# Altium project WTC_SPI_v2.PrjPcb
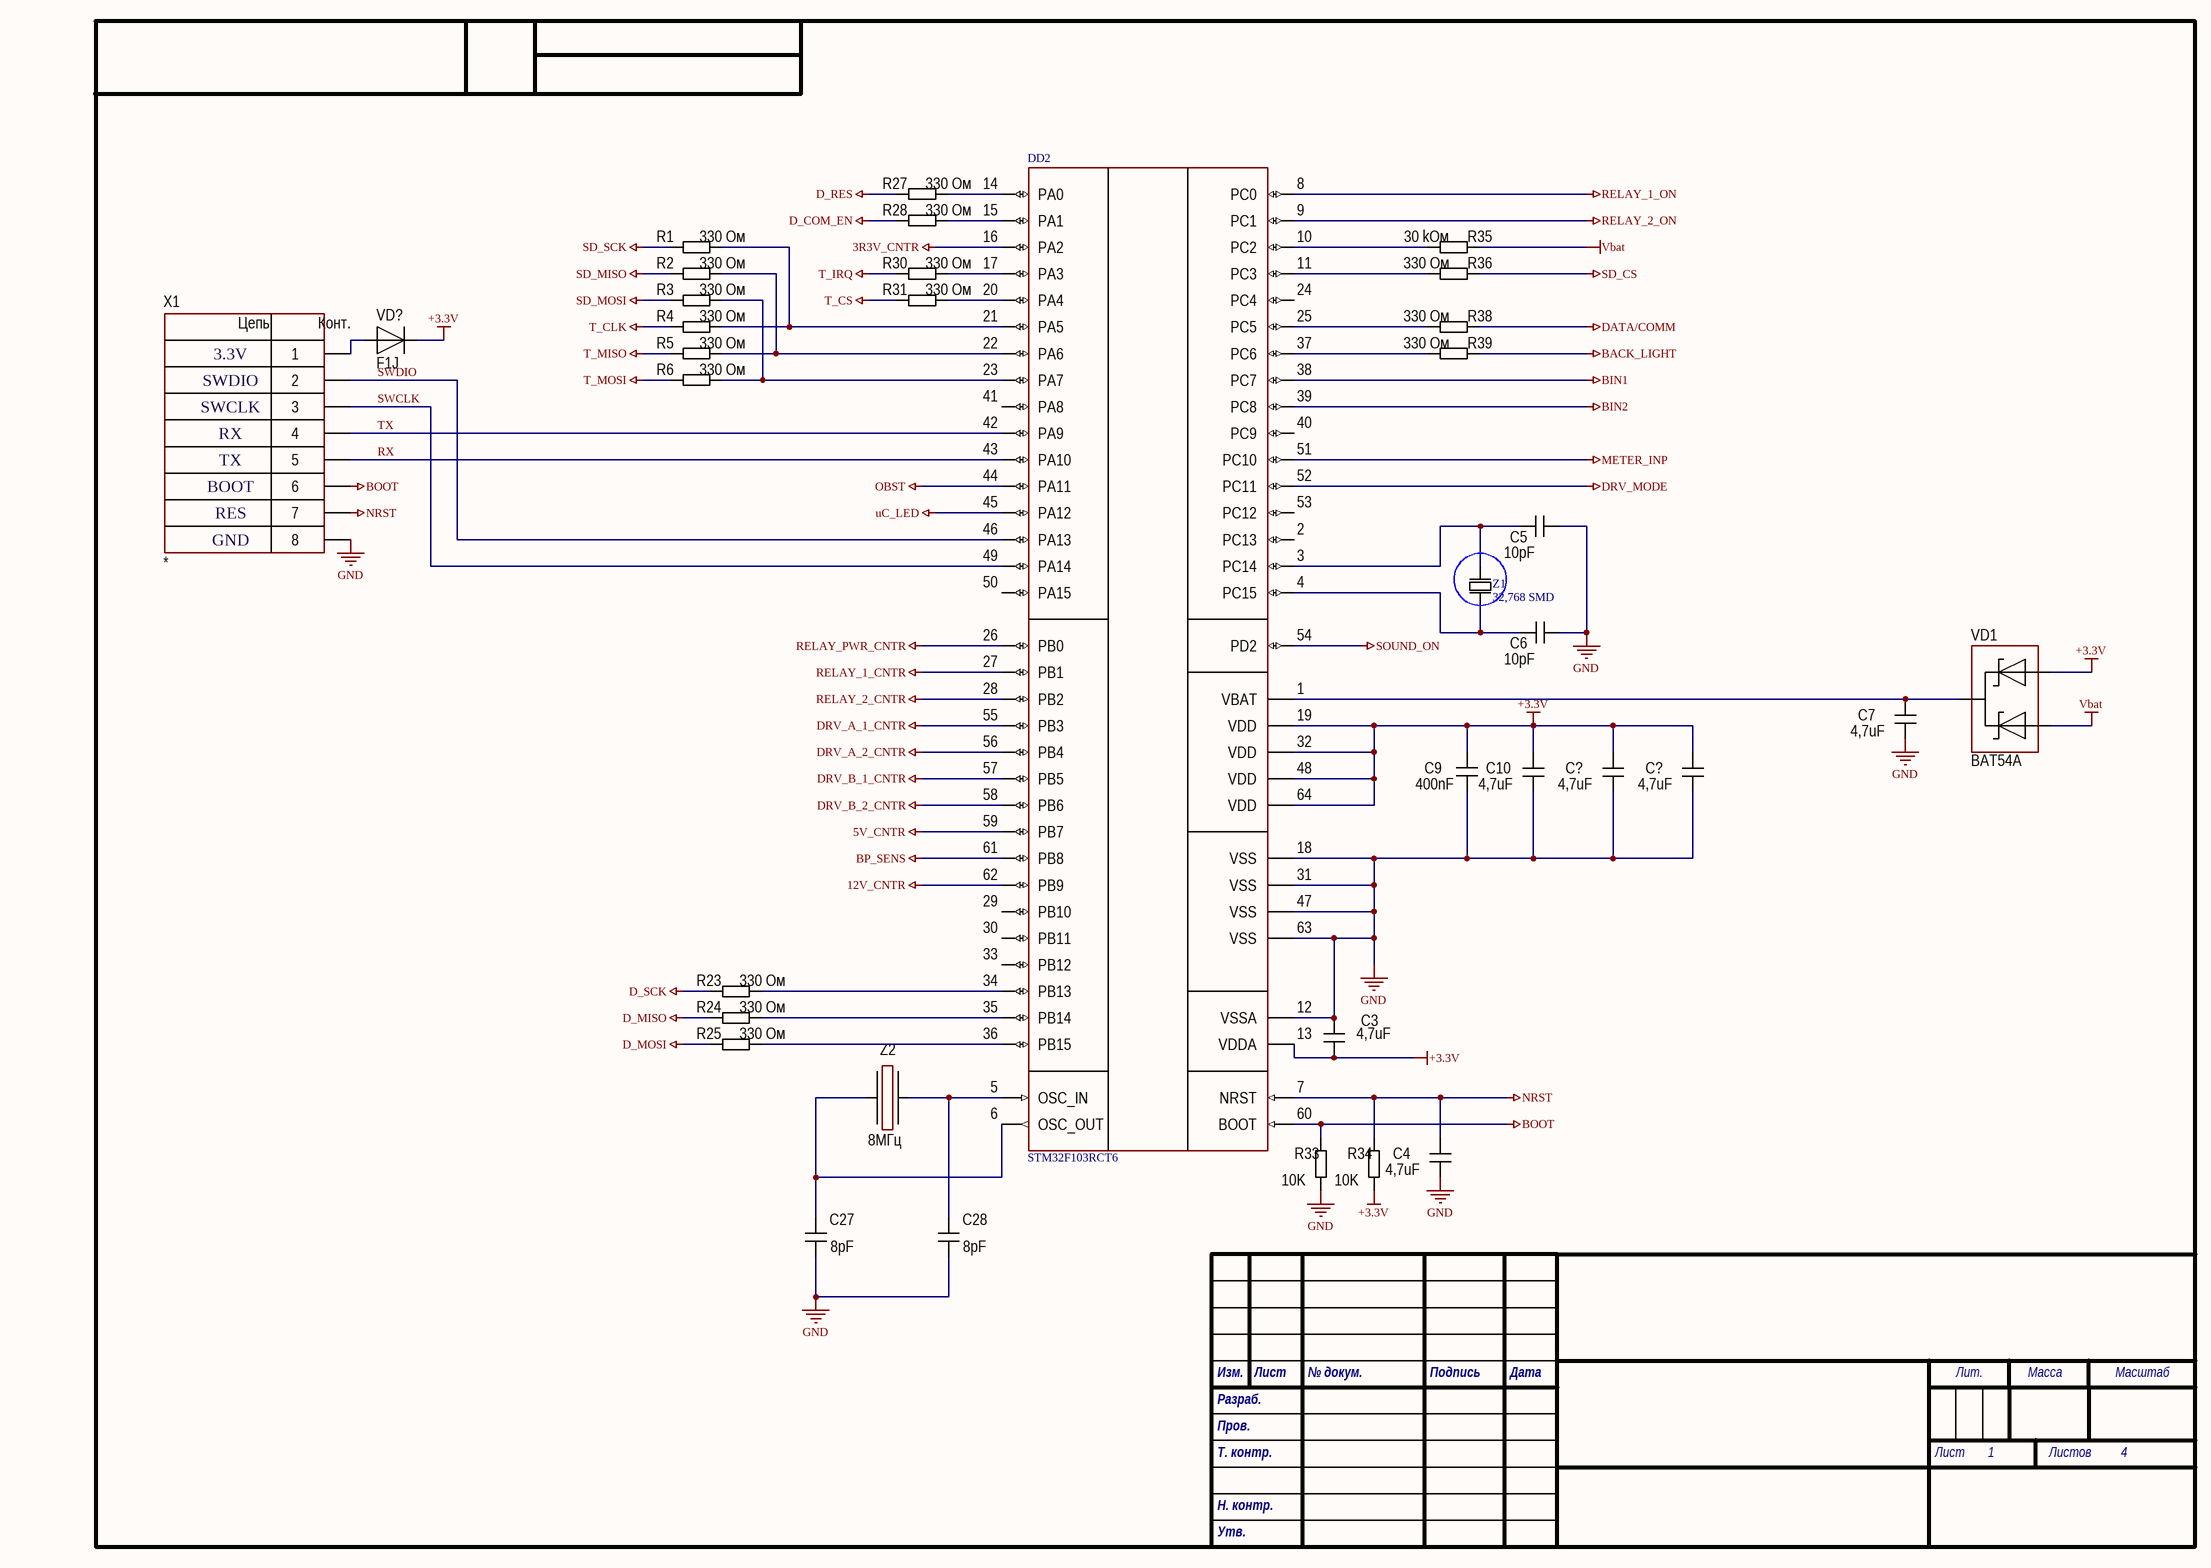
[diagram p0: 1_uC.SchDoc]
4 sheets, 138 parts. Net scope: global (net labels, ports and power ports of the same name join across sheets).
Sheets:
  1_uC.SchDoc
  2_PowerPerif.SchDoc
  3_InfoPerif.SchDoc
  4_PowerSupplie.SchDoc

## Sheet 1_uC.SchDoc
size 414 x 293 mm; SheetNumber: 1; SheetTotal: 4

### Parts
(Parts that share a designator on the sheet are numbered #1, #2 ... from top to bottom, then left to right.)
C3  4,7uF  [CH0402C]
C4  4,7uF  [CH0402C]
C5  10pF  [CH0402C]
C6  10pF  [CH0402C]
C7  4,7uF  [CH0402C]
C9  400nF  [CH0402C]
C10  4,7uF  [CH0402C]
C27  8pF  [CH0402C]
C28  8pF  [CH0402C]
C?#1  4,7uF  [CH0402C]
C?#2  4,7uF  [CH0402C]
DD2  STM32F103RCT6  [64-LQFP]
R1  330 Ом  [CH0603R]
R2  330 Ом  [CH0603R]
R3  330 Ом  [CH0603R]
R4  330 Ом  [CH0603R]
R5  330 Ом  [CH0603R]
R6  330 Ом  [CH0603R]
R23  330 Ом  [CH0603R]
R24  330 Ом  [CH0603R]
R25  330 Ом  [CH0603R]
R27  330 Ом  [CH0603R]
R28  330 Ом  [CH0603R]
R30  330 Ом  [CH0603R]
R31  330 Ом  [CH0603R]
R33  10K  [CH0805R]
R34  10K  [CH0805R]
R35  30 kОм  [CH0603R]
R36  330 Ом  [CH0603R]
R38  330 Ом  [CH0603R]
R39  330 Ом  [CH0603R]
VD1  BAT54A  [SOT23_123]
VD?#1  F1J  [SOD123F]
X1  *  [CON: PLS-8]
Z1  32,768 SMD  [SMD 32.768KHz]
Z2  8МГц  [OSC: ABM3]

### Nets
3R3V_CNTR: DD2.16(PA2)
5V_CNTR: DD2.59(PB7)
12V_CNTR: DD2.62(PB9)
+3.3V: C3.1 C9.1 C10.2 C?#1.2 C?#2.2 DD2.13(VDDA) DD2.19(VDD) DD2.32(VDD) DD2.48(VDD) DD2.64(VDD) R34.1 VD1.1 VD?#1.2
BACK_LIGHT: R39.1
BIN1: DD2.38(PC7)
BIN2: DD2.39(PC8)
BOOT: DD2.60(BOOT) R33.2 X1.6
BP_SENS: DD2.61(PB8)
D_COM_EN: R28.1
D_MISO: R24.1
D_MOSI: R25.1
D_RES: R27.1
D_SCK: R23.1
DATA/COMM: R38.1
DRV_A_1_CNTR: DD2.55(PB3)
DRV_A_2_CNTR: DD2.56(PB4)
DRV_B_1_CNTR: DD2.57(PB5)
DRV_B_2_CNTR: DD2.58(PB6)
DRV_MODE: DD2.52(PC11)
GND: C3.2 C4.1 C5.2 C6.1 C7.1 C9.2 C10.1 C27.1 C28.1 C?#1.1 C?#2.1 DD2.12(VSSA) DD2.18(VSS) DD2.31(VSS) DD2.47(VSS) DD2.63(VSS) R33.1 X1.8
METER_INP: DD2.51(PC10)
NRST: C4.2 DD2.7(NRST) R34.2 X1.7
OBST: DD2.44(PA11)
RELAY_1_CNTR: DD2.27(PB1)
RELAY_1_ON: DD2.8(PC0)
RELAY_2_CNTR: DD2.28(PB2)
RELAY_2_ON: DD2.9(PC1)
RELAY_PWR_CNTR: DD2.26(PB0)
RX: DD2.43(PA10) X1.5
SD_CS: R36.1
SD_MISO: R2.1
SD_MOSI: R3.1
SD_SCK: R1.1
SOUND_ON: DD2.54(PD2)
T_CLK: R4.1
T_CS: R31.1
T_IRQ: R30.1
T_MISO: R5.1
T_MOSI: R6.1
TX: DD2.42(PA9) X1.4
uC_LED: DD2.45(PA12)
Vbat: R35.1 VD1.3
SWCLK: DD2.49(PA14) X1.3
SWDIO: DD2.46(PA13) X1.2
NetC5_1: C5.1 DD2.3(PC14) Z1.1
NetC6_2: C6.2 DD2.4(PC15) Z1.2
NetC7_2: C7.2 DD2.1(VBAT) VD1.2
NetC27_2: C27.2 DD2.6(OSC_OUT) Z2.1
NetC28_2: C28.2 DD2.5(OSC_IN) Z2.3
NetDD2_10: DD2.10(PC2) R35.2
NetDD2_11: DD2.11(PC3) R36.2
NetDD2_14: DD2.14(PA0) R27.2
NetDD2_15: DD2.15(PA1) R28.2
NetDD2_17: DD2.17(PA3) R30.2
NetDD2_20: DD2.20(PA4) R31.2
NetDD2_21: DD2.21(PA5) R1.2 R4.2
NetDD2_22: DD2.22(PA6) R2.2 R5.2
NetDD2_23: DD2.23(PA7) R3.2 R6.2
NetDD2_25: DD2.25(PC5) R38.2
NetDD2_34: DD2.34(PB13) R23.2
NetDD2_35: DD2.35(PB14) R24.2
NetDD2_36: DD2.36(PB15) R25.2
NetDD2_37: DD2.37(PC6) R39.2
NetVD?#1_1: VD?#1.1 X1.1

Not connected (* = marked no-connect by the designer): DD2 2(PC13) 24(PC4) 29(PB10) 30(PB11) 33(PB12) 40(PC9) 41(PA8) 50(PA15) 53(PC12)

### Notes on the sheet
- 3.3V
- SWDIO
- SWCLK
- RX
- TX
- BOOT
- RES
- GND

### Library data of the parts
C3-C6 C9 C10 C27 C28 C?#1 C?#2 = Capacitor: 0402
C7 = Capacitor
DD2 = STM32F103RCT6: Cortex-M3 (64-LQFP)
R1-R6 R23-R25 R27 R28 R30 R31 R35 R36 R38 R39 = Resistor: 0603
R33 R34 = Resistor: 0805
VD1 = Diod Schottky Array v.1: SOT-23
VD?#1 = Diod
X1 = 8-Connector: Pin header 8
Z1 = Kvarc_32,768: 32,768 kHz SMD 8mm x 3.8mm 12,5pF
Z2 = Oscillator: NX5032GA-8MHz

## Sheet 2_PowerPerif.SchDoc
size 414 x 293 mm; SheetNumber: 2; SheetTotal: 4
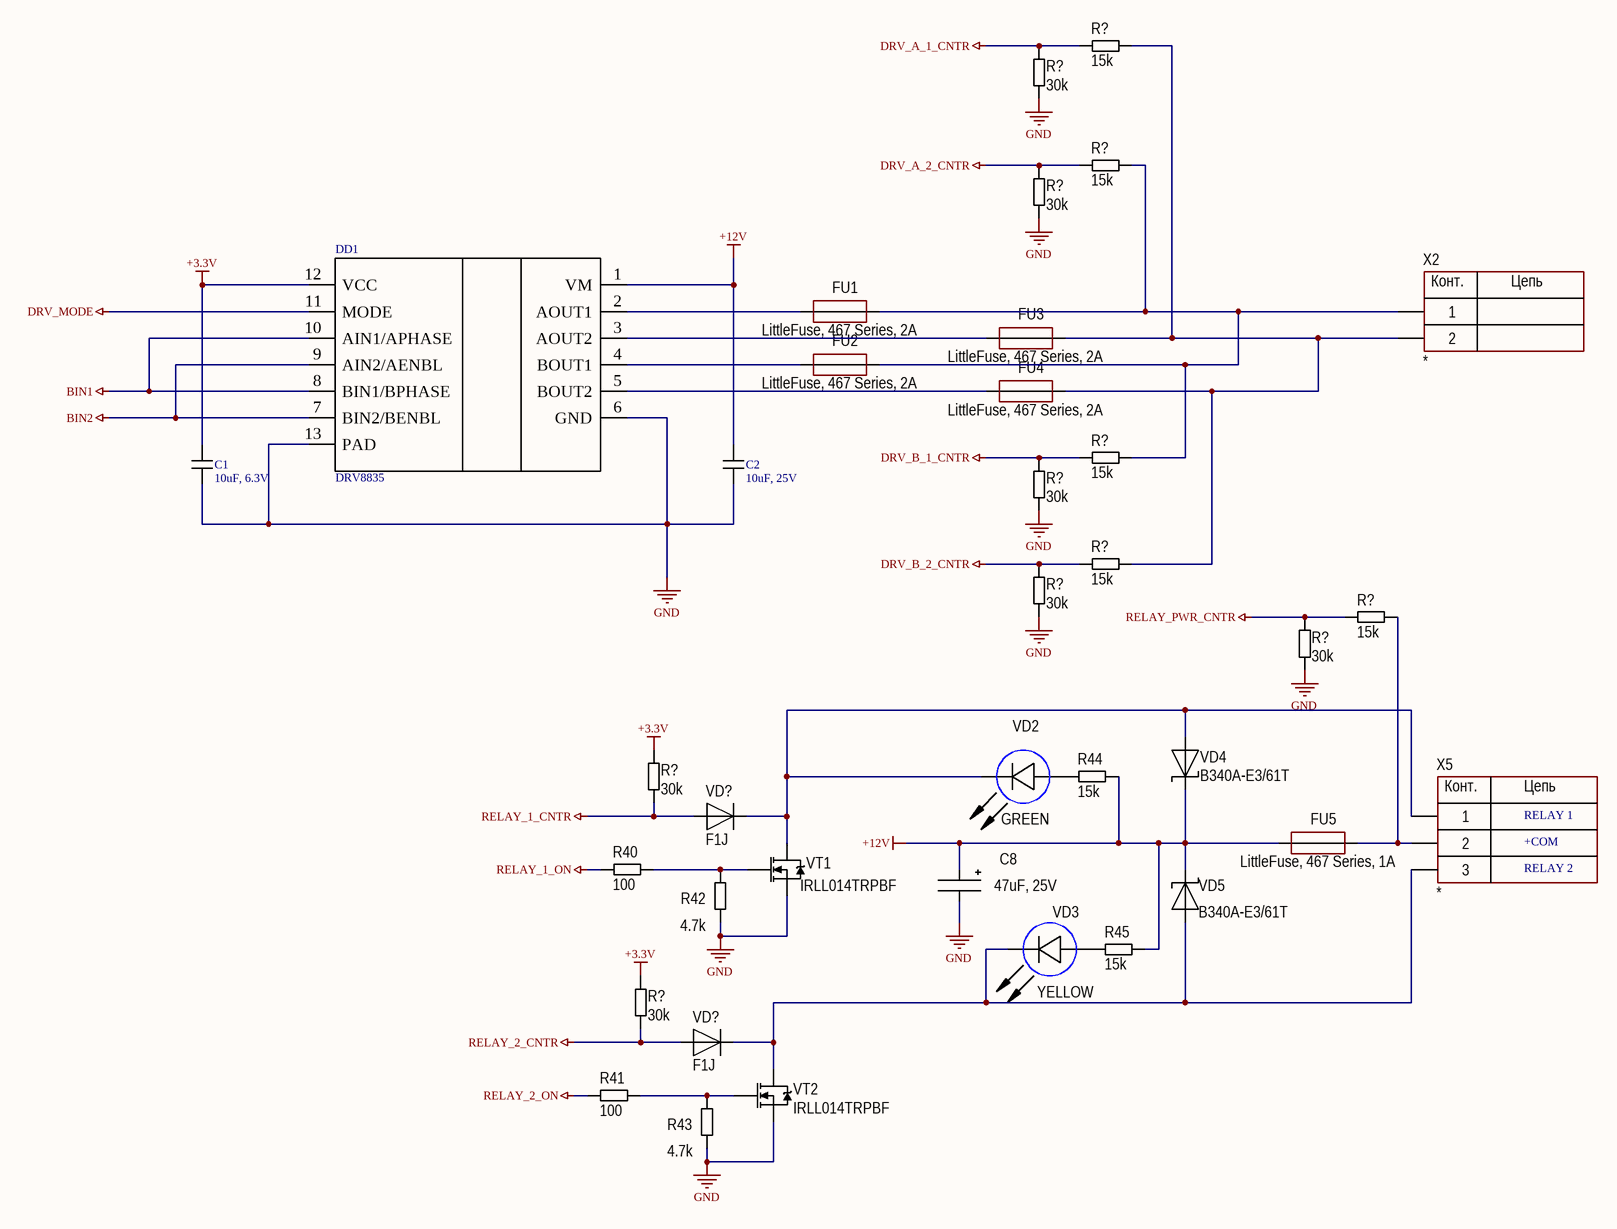
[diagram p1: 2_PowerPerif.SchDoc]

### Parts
(Parts that share a designator on the sheet are numbered #1, #2 ... from top to bottom, then left to right.)
C1  10uF, 6.3V  [C_0603]
C2  10uF, 25V  [C_0603]
C8  47uF, 25V  [D8C3.2H12]
DD1  DRV8835  [WSON12]
FU1  LittleFuse, 467 Series, 2A  [CH0603F]
FU2  LittleFuse, 467 Series, 2A  [CH0603F]
FU3  LittleFuse, 467 Series, 2A  [CH0603F]
FU4  LittleFuse, 467 Series, 2A  [CH0603F]
FU5  LittleFuse, 467 Series, 1A  [CH0603F]
R40  100  [CH0805R]
R41  100  [CH0805R]
R42  4.7k  [CH0805R]
R43  4.7k  [CH0805R]
R44  15k  [CH0805R]
R45  15k  [CH0805R]
R?#1  15k  [CH0805R]
R?#2  30k  [CH0805R]
R?#3  15k  [CH0805R]
R?#4  30k  [CH0805R]
R?#5  15k  [CH0805R]
R?#6  30k  [CH0805R]
R?#7  15k  [CH0805R]
R?#8  15k  [CH0805R]
R?#9  30k  [CH0805R]
R?#10  30k  [CH0805R]
R?#11  30k  [CH0805R]
R?#12  30k  [CH0805R]
VD2  GREEN  [CH0603LB]
VD3  YELLOW  [CH0603LB]
VD4  B340A-E3/61T  [SMA]
VD5  B340A-E3/61T  [SMA]
VD?#2  F1J  [SOD123F]
VD?#3  F1J  [SOD123F]
VT1  IRLL014TRPBF  [SOT223]
VT2  IRLL014TRPBF  [SOT223]
X2  *  [CON: CWF-2]
X5  *  [CON: 300-03P-5.0]

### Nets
+3.3V: C1.2 DD1.12(VCC) R?#11.2 R?#12.2
+12V: C2.2 C8.1 DD1.1(VM) FU5.1 R44.2 R45.2 VD4.2 VD5.2
BIN1: DD1.8(BIN1/BPHASE) DD1.10(AIN1/APHASE)
BIN2: DD1.7(BIN2/BENBL) DD1.9(AIN2/AENBL)
DRV_A_1_CNTR: R?#1.1 R?#2.2
DRV_A_2_CNTR: R?#3.1 R?#4.2
DRV_B_1_CNTR: R?#5.1 R?#6.2
DRV_B_2_CNTR: R?#7.1 R?#9.2
DRV_MODE: DD1.11(MODE)
GND: C1.1 C2.1 C8.2 DD1.6(GND) DD1.13(PAD) R42.1 R43.1 R?#2.1 R?#4.1 R?#6.1 R?#9.1 R?#10.1 VT1.3(S) VT2.3(S)
RELAY_1_CNTR: R?#11.1 VD?#2.1
RELAY_1_ON: R40.2
RELAY_2_CNTR: R?#12.1 VD?#3.1
RELAY_2_ON: R41.2
RELAY_PWR_CNTR: R?#8.1 R?#10.2
NetDD1_2: DD1.2(AOUT1) FU1.1
NetDD1_3: DD1.3(AOUT2) FU3.1
NetDD1_4: DD1.4(BOUT1) FU2.1
NetDD1_5: DD1.5(BOUT2) FU4.1
NetFU1_2: FU1.2 FU2.2 R?#3.2 R?#5.2 X2.1
NetFU3_2: FU3.2 FU4.2 R?#1.2 R?#7.2 X2.2
NetFU5_2: FU5.2 R?#8.2 X5.2
NetR40_1: R40.1 R42.2 VT1.1(G)
NetR41_1: R41.1 R43.2 VT2.1(G)
NetR44_1: R44.1 VD2.1(A)
NetR45_1: R45.1 VD3.1(A)
NetVD2_2: VD2.2(C) VD4.1 VD?#2.2 VT1.2(D) X5.1
NetVD3_2: VD3.2(C) VD5.1 VD?#3.2 VT2.2(D) X5.3

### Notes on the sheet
- RELAY 1
- +COM
- RELAY 2

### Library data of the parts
C1 C2 = C_SMD
C8 = AlumCap
DD1 = DRV8835: Driver
FU1-FU5 = Fuse
R40-R45 R?#1-R?#12 = Resistor
VD2 VD3 = LED_1
VD4 VD5 = Diod Schottky
VD?#2 VD?#3 = Diod
VT1 VT2 = N-chanel: Mosfet
X2 = 2-Connector
X5 = 3-Connector

## Sheet 3_InfoPerif.SchDoc
size 414 x 293 mm; SheetNumber: 3; SheetTotal: 4
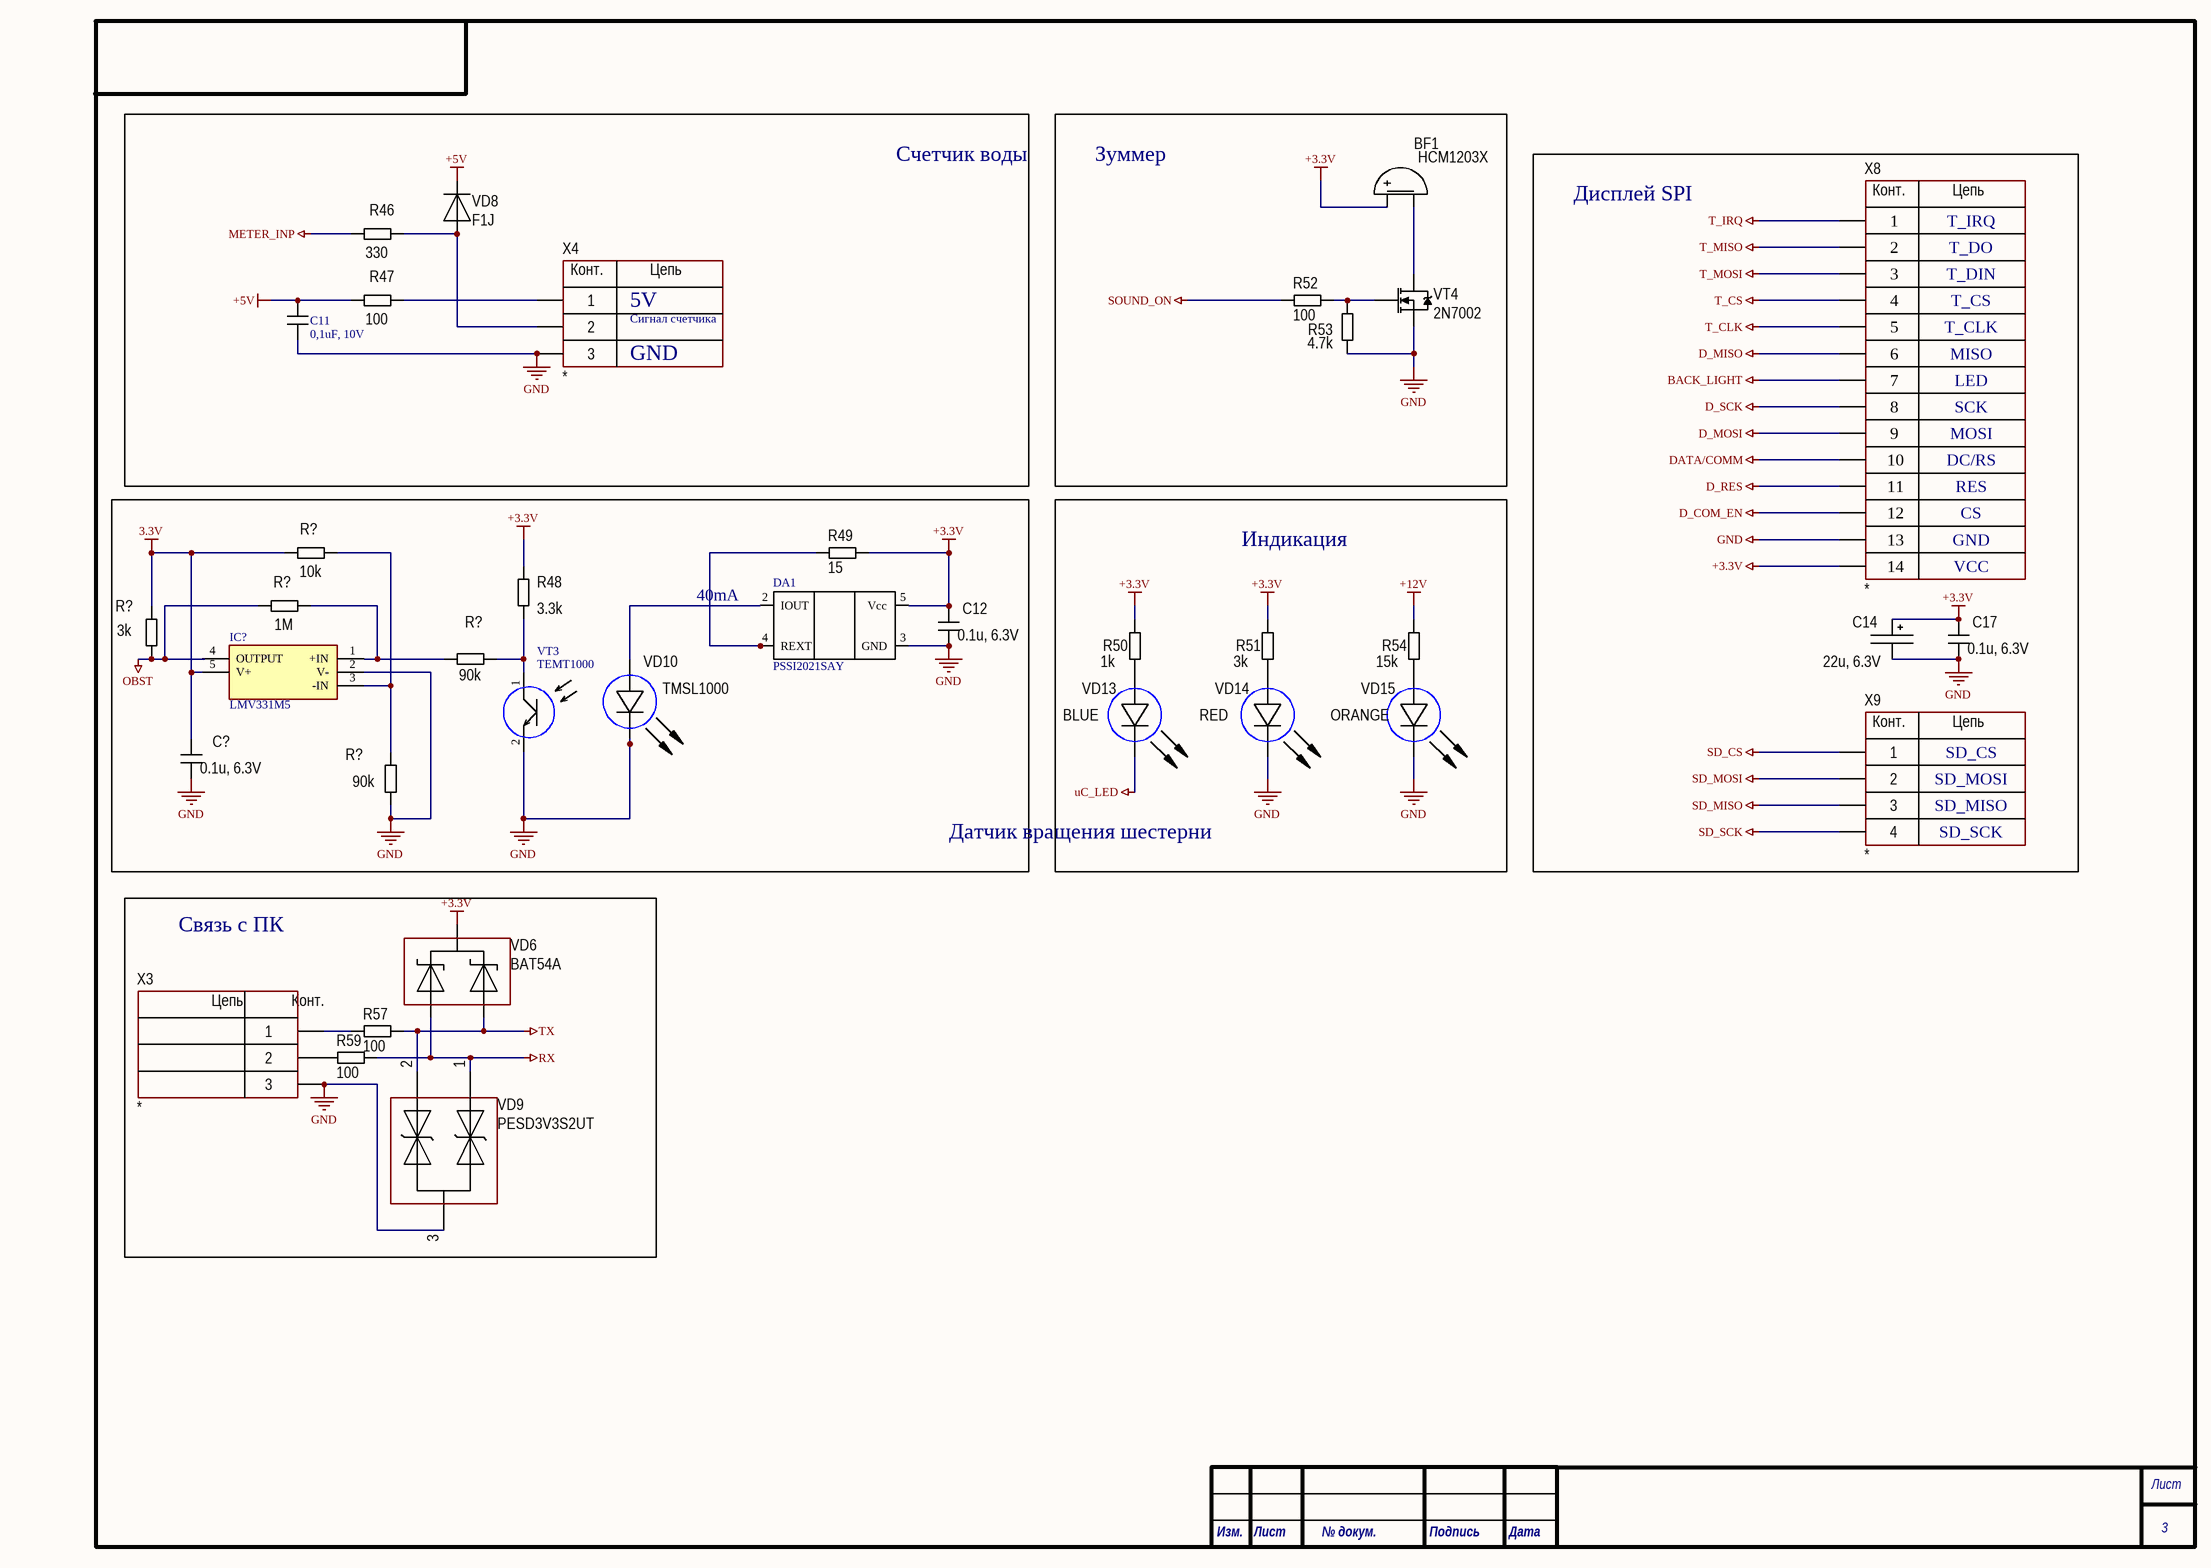
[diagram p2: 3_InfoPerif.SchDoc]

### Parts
(Parts that share a designator on the sheet are numbered #1, #2 ... from top to bottom, then left to right.)
BF1  HCM1203X  [BUZ: AI-1223-TWT-3V-2-R]
C11  0,1uF, 10V  [C_0603]
C12  0.1u, 6.3V  [CH0805C]
C14  22u, 6.3V  [TANTAL_B]
C17  0.1u, 6.3V  [CH0805C]
C?#3  0.1u, 6.3V  [CH0805C]
DA1  PSSI2021SAY  [SOT353]
IC?  LMV331M5  [SOT95P280X145-5N]
R46  330  [CH0805R]
R47  100  [CH2512R]
R48  3.3k  [CH0805R]
R49  15  [CH0805R]
R50  1k  [CH0805R]
R51  3k  [CH0805R]
R52  100  [CH0805R]
R53  4.7k  [CH0805R]
R54  15k  [CH0805R]
R57  100  [CH0805R]
R59  100  [CH0805R]
R?#13  10k  [CH0805R]
R?#14  1M  [CH0805R]
R?#15  90k  [CH0805R]
R?#16  3k  [CH0805R]
R?#17  90k  [CH0805R]
VD6  BAT54A  [SOT23_123]
VD8  F1J  [SOD123F]
VD9  PESD3V3S2UT  [SOT23_132]
VD10  TMSL1000  [TSML1000]
VD13  BLUE  [CH0603LB]
VD14  RED  [CH0603LB]
VD15  ORANGE  [CH0603LB]
VT3  TEMT1000  [TEMT1000]
VT4  2N7002  [SOT23_123]
X3  *  [CON: CWF-3]
X4  *  [CON: CWF-3]
X8  *  [DS1024-14]
X9  *  [DS1023-4]

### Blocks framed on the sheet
Зуммер: BF1 R52 R53 VT4
Дисплей SPI: C14 C17 X8 X9
Датчик вращения шестерни: C12 C?#3 DA1 IC? R48 R49 R?#13-R?#17 VD10 VT3
Индикация: R50 R51 R54 VD13-VD15
Связь с ПК: R57 R59 VD6 VD9 X3

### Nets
3.3V: C?#3.2 IC?.5(V+) R?#13.2 R?#16.2
+3.3V: BF1.1(+) C12.2 C14.1 C17.2 R48.2 R49.2 R50.2 R51.2 VD6.2 X8.14
+5V: C11.2 R47.1 VD8.2
+12V: R54.2
BACK_LIGHT: X8.7
D_COM_EN: X8.12
D_MISO: X8.6
D_MOSI: X8.9
D_RES: X8.11
D_SCK: X8.8
DATA/COMM: X8.10
GND: C11.1 C12.1 C14.2 C17.1 C?#3.1 DA1.3(GND) IC?.2(V-) R53.1 R?#17.1 VD9.3 VD10.2(C) VD14.2(C) VD15.2(C) VT3.2 VT4.3(S) X3.3 X4.3 X8.13
METER_INP: R46.1
OBST: IC?.4(OUTPUT) R?#14.2 R?#16.1
RX: R59.2 VD6.3 VD9.1
SD_CS: X9.1
SD_MISO: X9.3
SD_MOSI: X9.2
SD_SCK: X9.4
SOUND_ON: R52.2
T_CLK: X8.5
T_CS: X8.4
T_IRQ: X8.1
T_MISO: X8.2
T_MOSI: X8.3
TX: R57.2 VD6.1 VD9.2
uC_LED: VD13.2(C)
NetBF1_2: BF1.2(-) VT4.2(D)
NetDA1_2: DA1.2(IOUT) VD10.1(A)
NetDA1_4: DA1.4(REXT) R49.1
NetIC?_1: IC?.1(+IN) R?#14.1 R?#15.2
NetIC?_3: IC?.3(-IN) R?#13.1 R?#17.2
NetR46_2: R46.2 VD8.1 X4.2
NetR47_2: R47.2 X4.1
NetR48_1: R48.1 R?#15.1 VT3.1
NetR50_1: R50.1 VD13.1(A)
NetR51_1: R51.1 VD14.1(A)
NetR52_1: R52.1 R53.2 VT4.1(G)
NetR54_1: R54.1 VD15.1(A)
NetR57_1: R57.1 X3.1
NetR59_1: R59.1 X3.2

Not connected (* = marked no-connect by the designer): DA1 5(Vcc)

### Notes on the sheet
- Счетчик воды
- T_IRQ
- 5V
- T_DO
- T_DIN
- T_CS
- GND
- Сигнал счетчика
- T_CLK
- MISO
- LED
- SCK
- MOSI
- DC/RS
- RES
- CS
- VCC
- 40mA
- SD_CS
- SD_MOSI
- SD_MISO
- SD_SCK

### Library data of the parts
BF1 = Buzzer: Manufacturer: PUI Audio, Inc.; Model: AI-1223-TWT-3V-2-R
C11 = C_SMD
C12 C?#3 = Capacitor: 0805
C14 = TantalCap
C17 = Capacitor
DA1 = PSSI2021SAY: Iout = 0.617/Rext + 15 µA
IC? = LMV331M5: Integrated Circuit; Manufacturer_Name: Texas Instruments
R46 R47 R50-R54 R57 R59 R?#13-R?#17 = Resistor
R48 R49 = Resistor: 0805
VD6 = Diod Schottky Array v.1
VD8 = Diod
VD9 = TVS Array
VD10 VD13-VD15 = LED_1
VT4 = N-chanel: Mosfet
X3 X4 = 3-Connector
X8 = 14-Connector
X9 = 4-Connector

## Sheet 4_PowerSupplie.SchDoc
size 414 x 293 mm; SheetNumber: 4; SheetTotal: 4; PageSetup: Record=PageOptionsZCenterHorizontal=TrueZCenterVertical=TrueZPrintScale=1.00ZXCorrection=0.00ZYCorrection=0.00ZPrintKind=1ZBorderSize=5000000ZLeftOffset=0ZBottomOffset=0ZOrientation=2ZPaperLength=1000ZPaperWidth=1000ZScale=100ZPaperSource=7ZPrintQuality=-4ZMediaType=1ZDitherType=10ZPaperKind=A3ZPrintScaleMode=0; Razrabotal: {Разработал}; Proveril: {Проверил}; Tkontr: {Т.контр.}; Nkontr: {Н.контр.}; Ytverdil: {Утвердил}; Nazvanie1: {Название1}; Nazvanie2: {Название2}; Oboznachenie: {Обозначение}
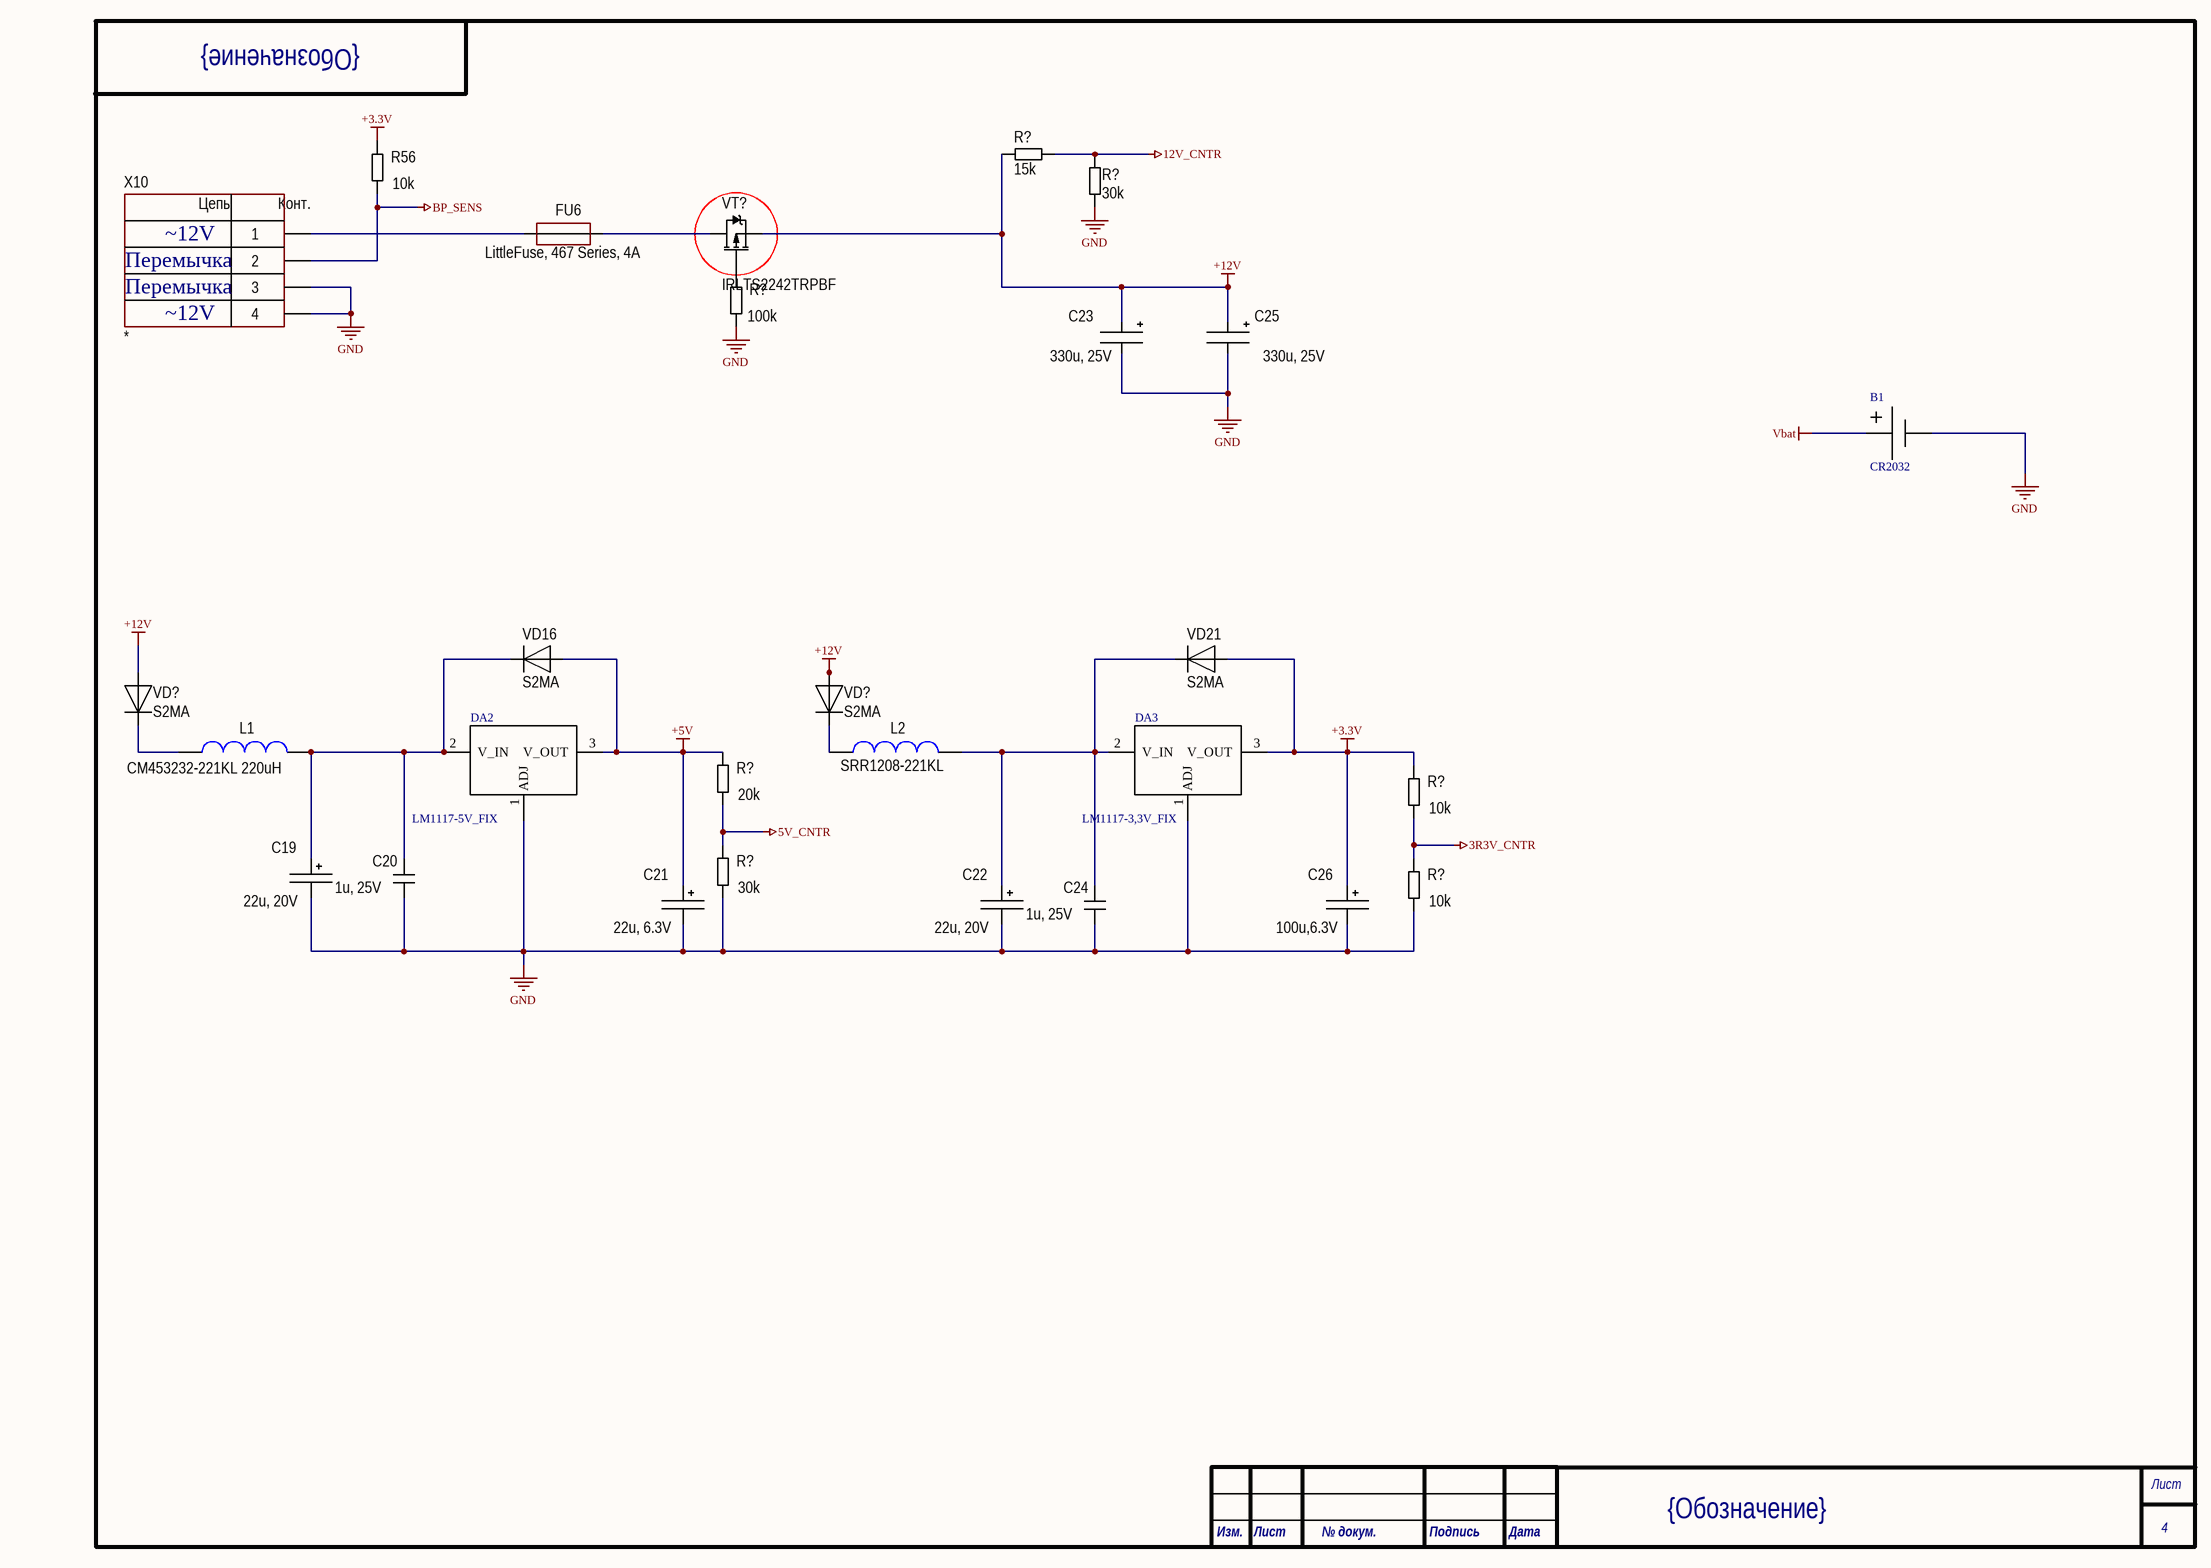
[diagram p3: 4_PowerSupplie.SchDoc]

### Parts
(Parts that share a designator on the sheet are numbered #1, #2 ... from top to bottom, then left to right.)
B1  CR2032  [CR2032]
C19  22u, 20V  [TANTAL_B]
C20  1u, 25V  [CH0805C]
C21  22u, 6.3V  [TANTAL_B]
C22  22u, 20V  [TANTAL_B]
C23  330u, 25V  [D10C4.4H10]
C24  1u, 25V  [CH0805C]
C25  330u, 25V  [D10C4.4H10]
C26  100u,6.3V  [TANTAL_B]
DA2  LM1117-5V_FIX  [SOT223_123]
DA3  LM1117-3,3V_FIX  [SOT223_123]
FU6  LittleFuse, 467 Series, 4A  [CH0603F]
L1  CM453232-221KL 220uH  [IND:1812]
L2  SRR1208-221KL  [IND: SRR1208]
R56  10k  [CH0805R]
R?#18  15k  [CH0805R]
R?#19  30k  [CH0805R]
R?#20  100k  [CH0805R]
R?#21  20k  [CH0805R]
R?#22  10k  [CH0805R]
R?#23  30k  [CH0805R]
R?#24  10k  [CH0805R]
VD16  S2MA  [SMA]
VD21  S2MA  [SMA]
VD?#4  S2MA  [SMA]
VD?#5  S2MA  [SMA]
VT?  IRLTS2242TRPBF  [SOT223]
X10  *  [CON: CWF-4]

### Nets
3R3V_CNTR: R?#22.1 R?#24.2
5V_CNTR: R?#21.1 R?#23.2
12V_CNTR: R?#18.1 R?#19.2
+3.3V: C26.1 DA3.3(V_OUT) R56.2 R?#22.2 VD21.1
+5V: C21.1 DA2.3(V_OUT) R?#21.2 VD16.1
+12V: C23.1 C25.1 R?#18.2 VD?#4.1 VD?#5.1 VT?.3(S)
BP_SENS: R56.1 X10.2
GND: B1.2 C19.2 C20.1 C21.2 C22.2 C23.2 C24.1 C25.2 C26.2 DA2.1(ADJ) DA3.1(ADJ) R?#19.1 R?#20.1 R?#23.1 R?#24.1 X10.3 X10.4
Vbat: B1.1
NetC19_1: C19.1 C20.2 DA2.2(V_IN) L1.1 VD16.2
NetC22_1: C22.1 C24.2 DA3.2(V_IN) L2.1 VD21.2
NetFU6_1: FU6.1 X10.1
NetFU6_2: FU6.2 VT?.2(D)
NetL1_2: L1.2 VD?#4.2
NetL2_2: L2.2 VD?#5.2
NetR?#20_2: R?#20.2 VT?.1(G)

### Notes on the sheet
- Перемычка
- 2V

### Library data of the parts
B1 = Battery_CR2032
C19 C21 C22 C26 = TantalCap
C20 C24 = Capacitor
C23 C25 = AlumCap
DA2 DA3 = LM1117
FU6 = Fuse
L1 L2 = Inductor
R56 R?#18-R?#24 = Resistor
VD16 VD21 VD?#4 VD?#5 = Diod
VT? = P-chanel: Mosfet
X10 = 4-Connector

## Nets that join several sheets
3R3V_CNTR: 1_uC (DD2.16), 4_PowerSupplie (R?#22.1 R?#24.2)
5V_CNTR: 1_uC (DD2.59), 4_PowerSupplie (R?#21.1 R?#23.2)
12V_CNTR: 1_uC (DD2.62), 4_PowerSupplie (R?#18.1 R?#19.2)
+3.3V: 1_uC (13 pins), 2_PowerPerif (C1.2 DD1.12 R?#11.2 R?#12.2), 3_InfoPerif (10 pins), 4_PowerSupplie (5 pins)
+5V: 3_InfoPerif (C11.2 R47.1 VD8.2), 4_PowerSupplie (C21.1 DA2.3  R?#21.2 VD16.1)
+12V: 2_PowerPerif (8 pins), 3_InfoPerif (R54.2), 4_PowerSupplie (6 pins)
BACK_LIGHT: 1_uC (R39.1), 3_InfoPerif (X8.7)
BIN1: 1_uC (DD2.38), 2_PowerPerif (DD1.8 DD1.10)
BIN2: 1_uC (DD2.39), 2_PowerPerif (DD1.7 DD1.9)
BP_SENS: 1_uC (DD2.61), 4_PowerSupplie (R56.1 X10.2)
D_COM_EN: 1_uC (R28.1), 3_InfoPerif (X8.12)
D_MISO: 1_uC (R24.1), 3_InfoPerif (X8.6)
D_MOSI: 1_uC (R25.1), 3_InfoPerif (X8.9)
D_RES: 1_uC (R27.1), 3_InfoPerif (X8.11)
D_SCK: 1_uC (R23.1), 3_InfoPerif (X8.8)
DATA/COMM: 1_uC (R38.1), 3_InfoPerif (X8.10)
DRV_A_1_CNTR: 1_uC (DD2.55), 2_PowerPerif (R?#1.1 R?#2.2)
DRV_A_2_CNTR: 1_uC (DD2.56), 2_PowerPerif (R?#3.1 R?#4.2)
DRV_B_1_CNTR: 1_uC (DD2.57), 2_PowerPerif (R?#5.1 R?#6.2)
DRV_B_2_CNTR: 1_uC (DD2.58), 2_PowerPerif (R?#7.1 R?#9.2)
DRV_MODE: 1_uC (DD2.52), 2_PowerPerif (DD1.11)
GND: 1_uC (18 pins), 2_PowerPerif (14 pins), 3_InfoPerif (18 pins), 4_PowerSupplie (17 pins)
METER_INP: 1_uC (DD2.51), 3_InfoPerif (R46.1)
OBST: 1_uC (DD2.44), 3_InfoPerif (IC?.4 R?#14.2 R?#16.1)
RELAY_1_CNTR: 1_uC (DD2.27), 2_PowerPerif (R?#11.1 VD?#2.1)
RELAY_1_ON: 1_uC (DD2.8), 2_PowerPerif (R40.2)
RELAY_2_CNTR: 1_uC (DD2.28), 2_PowerPerif (R?#12.1 VD?#3.1)
RELAY_2_ON: 1_uC (DD2.9), 2_PowerPerif (R41.2)
RELAY_PWR_CNTR: 1_uC (DD2.26), 2_PowerPerif (R?#8.1 R?#10.2)
RX: 1_uC (DD2.43 X1.5), 3_InfoPerif (R59.2 VD6.3 VD9.1)
SD_CS: 1_uC (R36.1), 3_InfoPerif (X9.1)
SD_MISO: 1_uC (R2.1), 3_InfoPerif (X9.3)
SD_MOSI: 1_uC (R3.1), 3_InfoPerif (X9.2)
SD_SCK: 1_uC (R1.1), 3_InfoPerif (X9.4)
SOUND_ON: 1_uC (DD2.54), 3_InfoPerif (R52.2)
T_CLK: 1_uC (R4.1), 3_InfoPerif (X8.5)
T_CS: 1_uC (R31.1), 3_InfoPerif (X8.4)
T_IRQ: 1_uC (R30.1), 3_InfoPerif (X8.1)
T_MISO: 1_uC (R5.1), 3_InfoPerif (X8.2)
T_MOSI: 1_uC (R6.1), 3_InfoPerif (X8.3)
TX: 1_uC (DD2.42 X1.4), 3_InfoPerif (R57.2 VD6.1 VD9.2)
uC_LED: 1_uC (DD2.45), 3_InfoPerif (VD13.2)
Vbat: 1_uC (R35.1 VD1.3), 4_PowerSupplie (B1.1)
